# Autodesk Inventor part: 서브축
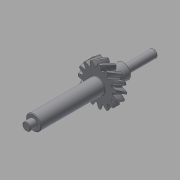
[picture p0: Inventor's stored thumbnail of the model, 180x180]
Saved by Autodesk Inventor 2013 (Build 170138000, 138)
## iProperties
Created: 2016-12
Part Number: 서브축
Material: 강철, 탄소
Document SubType Name: Modeling
Designer: mduedu
Categories: <?xml version="1.0" encoding="UTF-16"?> <MemberInstance><Categories><FamilyTemplate><FamilyTemplateParameter ValueType="xs:double" Id="1" ObjectReferenceKey="da
Density: 1 g/cm^3
CustomPartVersion: 1
Author: mduedu
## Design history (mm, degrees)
sketch "Sketch1"
  geometry: C1 r 19.321 at (0, 0)
  constraints: 1 centre point
  dimensions: "d0" = 38.64102 diameter of C1 (= da_da)
extrude "Extrusion1" new body sketch "Sketch1" distance "d1" = 10 (= da_b); taper "d2" = 0 deg
workplane "Work Plane2"
sketch "Sketch2"
  geometry: C1 r 19.321 at (0, 0) reference; C2 r 17.321 at (0, 0)
  constraints: 1 centre point, 1 coincident
  dimensions: "d3" = 34.64102 diameter of C2 (= da_dw)
feature "피치 지름" sketch "Sketch2" dims "d4" = 10, "d5" = 0
workplane "Work Plane8"
workplane "Work Plane9"
feature "스퍼 기어" dims "da_b" = 10, "da_d" = 34.64102, "da_aw" = 43.87862, "da_da" = 38.64102, "da_df" = 29.64102, "da_dw" = 34.64102, angle "da_beta" = 30 deg, "da_lefttooth" = 0, "da_righttooth" = 10
sketch "스케치3"
  geometry: C1 r 7.5 at (0, 0); 1 further point
  constraints: 1 centre point, 1 coincident
  dimensions: "d49" = 15 diameter of C1
extrude "돌출2" join sketch "스케치3" distance "d50" = 64; taper "d51" = 0 deg
sketch "스케치4"
  geometry: C1 r 4 at (0, 0); 1 further point
  constraints: 1 centre point, 1 coincident
  dimensions: "d52" = 8 diameter of C1
extrude "돌출3" join sketch "스케치4" distance "d53" = 7; taper "d54" = 0 deg
sketch "스케치5"
  geometry: C1 r 7.5 at (0, 0) reference; 1 further point
extrude "돌출4" join sketch "스케치5" distance "d55" = 16; taper "d56" = 0 deg
sketch "스케치6"
  geometry: C1 r 4 at (0, 0); 1 further point
  constraints: 1 centre point, 1 coincident
  dimensions: "d57" = 8 diameter of C1
extrude "돌출5" join sketch "스케치6" distance "d58" = 30; taper "d59" = 0 deg
chamfer "모따기1" distance "d60" = 0.5; stored, may be unused: second distance "d61" = 2, angle "d62" = 45 deg
fillet "모깎기1" dims "d63" = 0.5
body "Solid1"
body "Srf1"
other parameters: "d16" = 43.87862 (= da_aw), "d17" = 0, "d34" = 12 deg (computed from da_z), "d39" = 0, "d41" = 0, "d43" = 43.87862 (= da_aw), "d46" = 43.87862 (= da_aw), "d47" = 0, "d48" = 0
